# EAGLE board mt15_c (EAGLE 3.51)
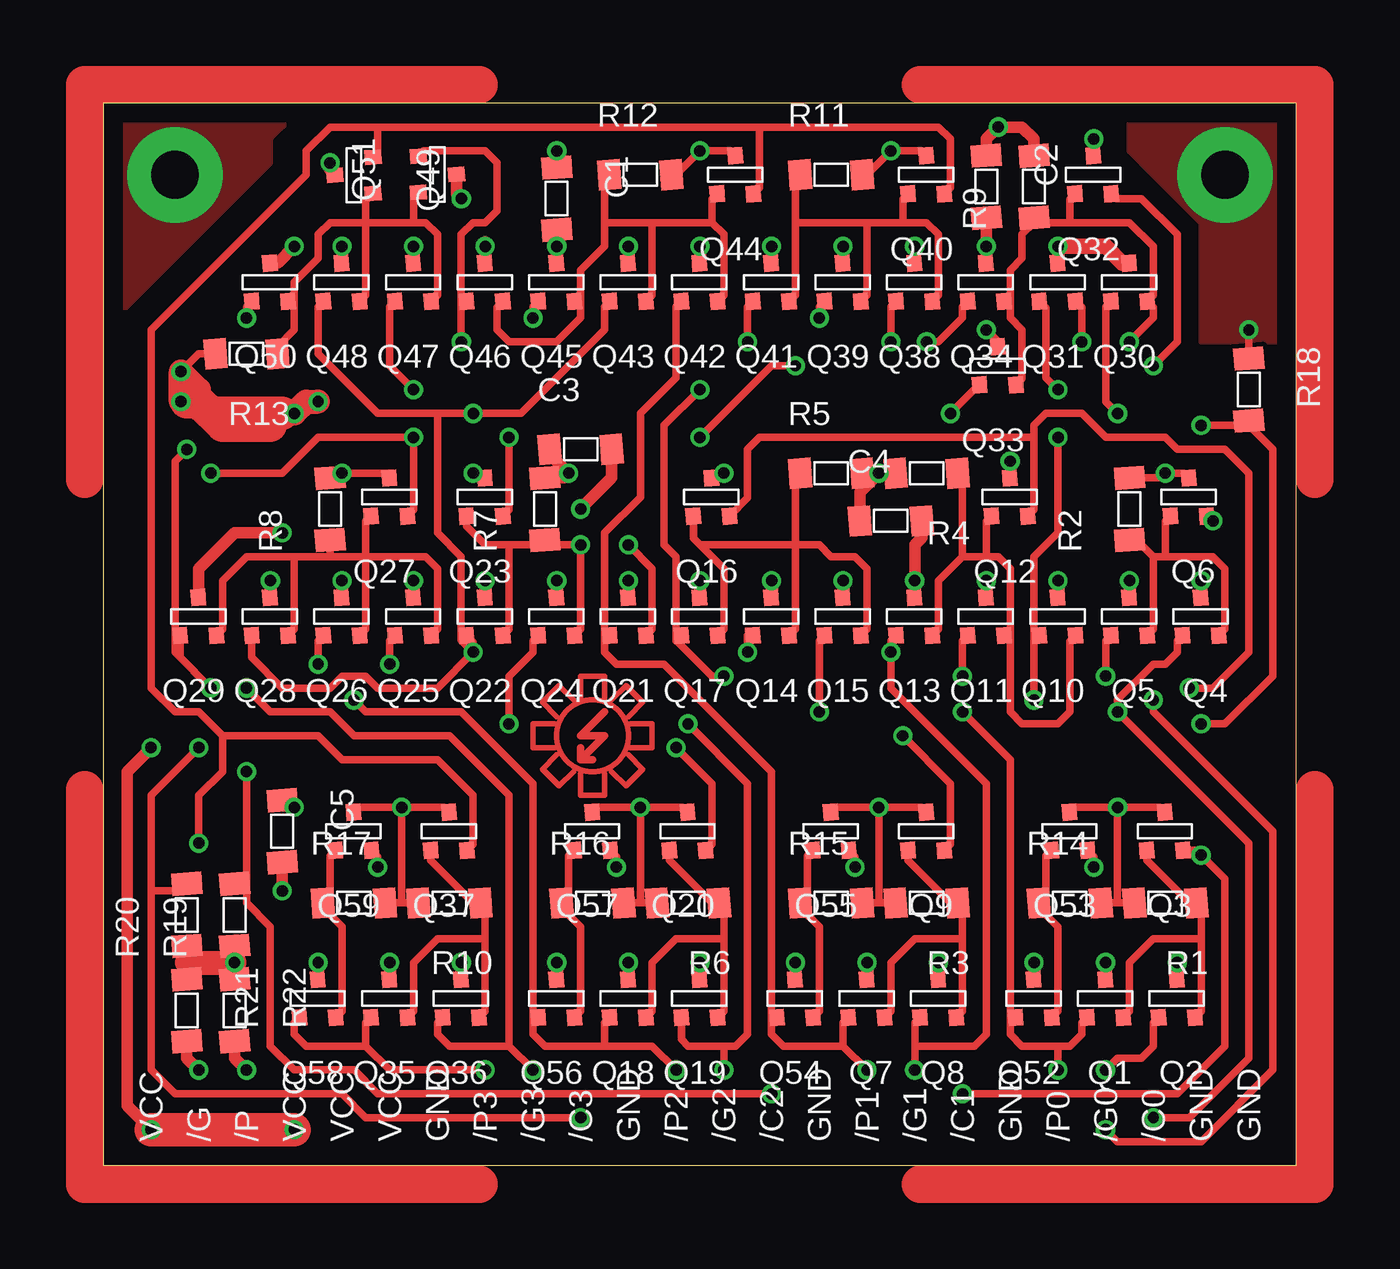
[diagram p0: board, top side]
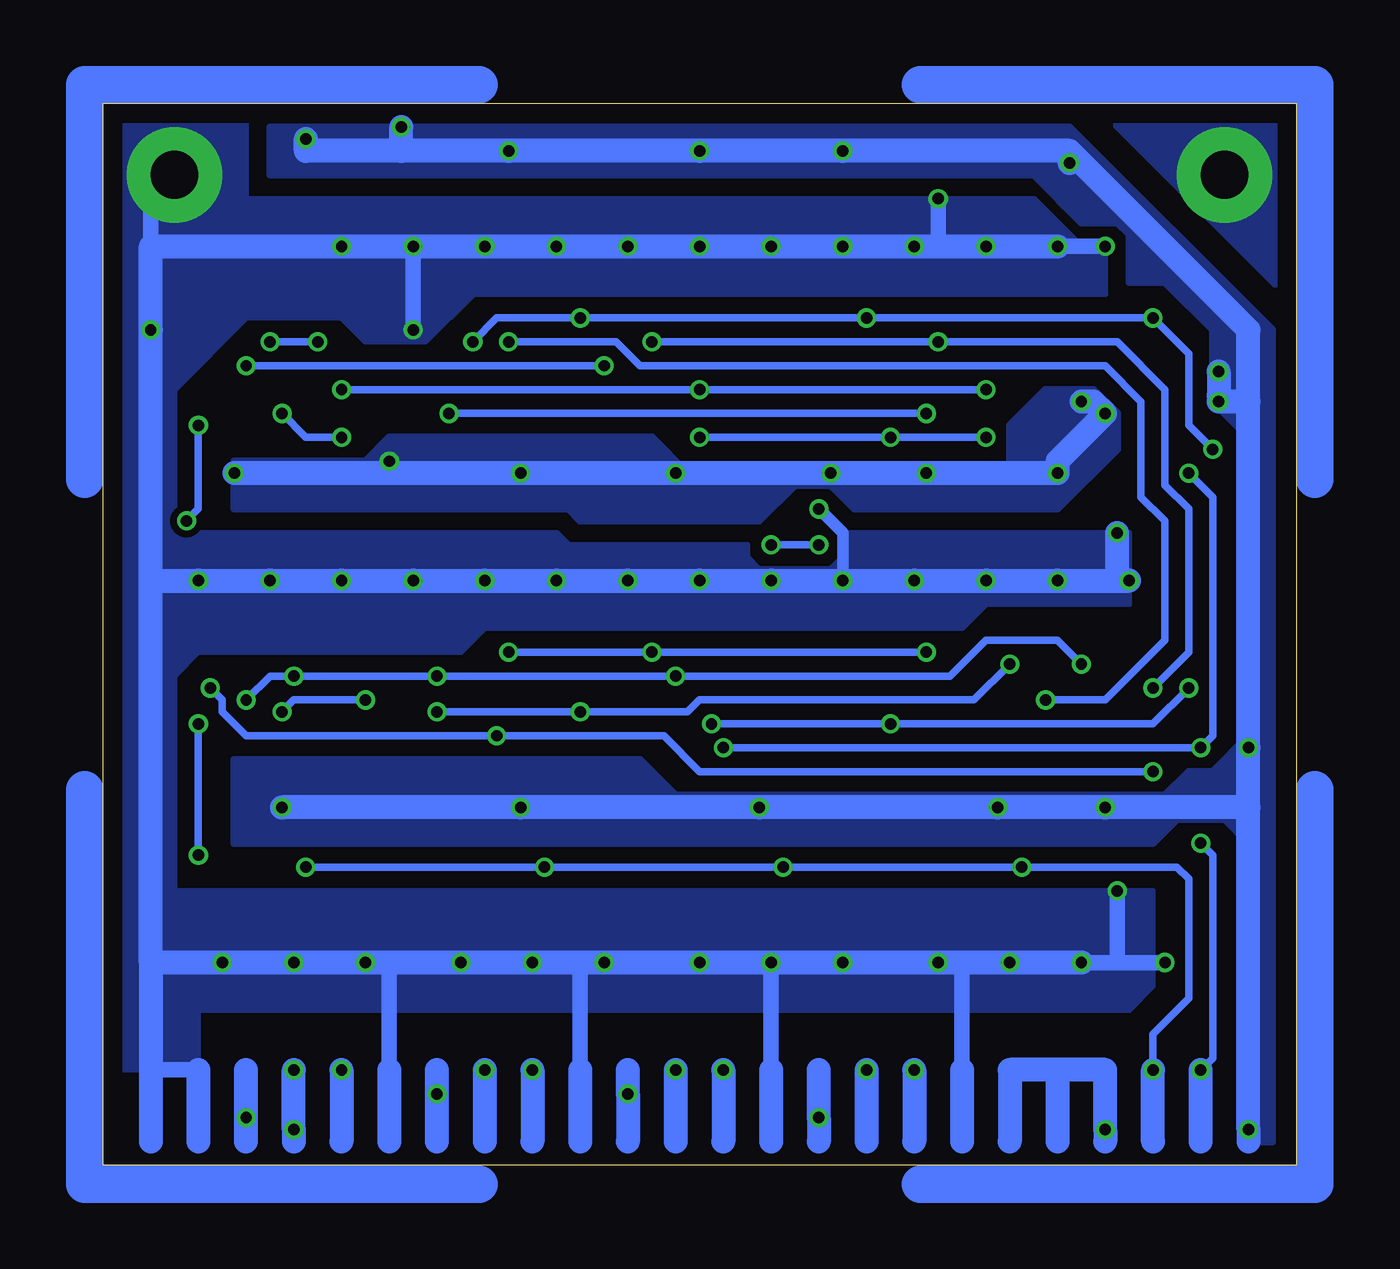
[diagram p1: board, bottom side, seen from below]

Size 63.48 x 56.5 mm. Coordinates in mm from the lower left corner, seen from the top.
Outline: 0,0 63.48,0 63.48,56.5 0,56.5 0,0
Copper layers used: Top, Bottom

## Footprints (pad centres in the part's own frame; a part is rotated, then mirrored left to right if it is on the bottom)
04 = smd 1.194 x 1.6 rotated 4.4:  1.651,0 | smd 1.194 x 1.6 rotated 4.3:  -1.651,0
T-23 = smd 0.787 x 0.889 rotated 4.4:  0.991,1.016 | smd 0.787 x 0.889 rotated 4.3:  -0.94,1.016 | smd 0.787 x 0.889 rotated 4.5:  0.025,-1.016

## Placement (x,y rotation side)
C1  100n  [04]  24.13,51.44 270 top
C2  100n  [04]  46.99,52.07 270 top
C3  100n  [04]  25.4,38.1 0 top
C4  100n  [04]  41.91,34.29 0 top
C5  100n  [04]  9.53,17.78 270 top
Q1  BC857  [T-23]  53.34,8.89 180 top
Q2  BC857  [T-23]  57.15,8.89 180 top
Q3  BC847  [T-23]  56.52,17.78 180 top
Q4  BC857  [T-23]  58.42,29.21 180 top
Q5  BC857  [T-23]  54.61,29.21 180 top
Q6  BC847  [T-23]  57.78,35.56 180 top
Q7  BC857  [T-23]  40.64,8.89 180 top
Q8  BC857  [T-23]  44.45,8.89 180 top
Q9  BC847  [T-23]  43.81,17.78 180 top
Q10  BC857  [T-23]  50.8,29.21 180 top
Q11  BC857  [T-23]  46.99,29.21 180 top
Q12  BC847  [T-23]  48.26,35.56 180 top
Q13  BC857  [T-23]  43.18,29.21 180 top
Q14  BC857  [T-23]  35.56,29.21 180 top
Q15  BC857  [T-23]  39.37,29.21 180 top
Q16  BC847  [T-23]  32.38,35.56 180 top
Q17  BC857  [T-23]  31.75,29.21 180 top
Q18  BC857  [T-23]  27.94,8.89 180 top
Q19  BC857  [T-23]  31.75,8.89 180 top
Q20  BC847  [T-23]  31.11,17.78 180 top
Q21  BC857  [T-23]  27.94,29.21 180 top
Q22  BC857  [T-23]  20.32,29.21 180 top
Q23  BC847  [T-23]  20.32,35.56 180 top
Q24  BC557  [T-23]  24.13,29.21 180 top
Q25  BC857  [T-23]  16.51,29.21 180 top
Q26  BC857  [T-23]  12.7,29.21 180 top
Q27  BC847  [T-23]  15.24,35.56 180 top
Q28  BC857  [T-23]  8.89,29.21 180 top
Q29  BC857  [T-23]  5.08,29.21 180 top
Q30  BC857  [T-23]  54.61,46.99 180 top
Q31  BC857  [T-23]  50.8,46.99 180 top
Q32  BC847  [T-23]  52.7,52.7 180 top
Q33  BC857  [T-23]  47.62,42.55 180 top
Q34  BC857  [T-23]  46.99,46.99 180 top
Q35  BC857  [T-23]  15.24,8.89 180 top
Q36  BC857  [T-23]  19.05,8.89 180 top
Q37  BC847  [T-23]  18.41,17.78 180 top
Q38  BC857  [T-23]  43.18,46.99 180 top
Q39  BC857  [T-23]  39.37,46.99 180 top
Q40  BC847  [T-23]  43.81,52.7 180 top
Q41  BC857  [T-23]  35.56,46.99 180 top
Q42  BC857  [T-23]  31.75,46.99 180 top
Q43  BC857  [T-23]  27.94,46.99 180 top
Q44  BC847  [T-23]  33.66,52.7 180 top
Q45  BC857  [T-23]  24.13,46.99 180 top
Q46  BC857  [T-23]  20.32,46.99 180 top
Q47  BC857  [T-23]  16.51,46.99 180 top
Q48  BC857  [T-23]  12.7,46.99 180 top
Q49  BC847  [T-23]  13.34,52.7 270 top
Q50  BC857  [T-23]  8.89,46.99 180 top
Q51  BC857  [T-23]  17.78,52.7 90 top
Q52  BC857  [T-23]  49.53,8.89 180 top
Q53  BC847  [T-23]  51.44,17.78 180 top
Q54  BC857  [T-23]  36.83,8.89 180 top
Q55  BC847  [T-23]  38.73,17.78 180 top
Q56  BC857  [T-23]  24.13,8.89 180 top
Q57  BC847  [T-23]  26.04,17.78 180 top
Q58  BC857  [T-23]  11.43,8.89 180 top
Q59  BC847  [T-23]  13.34,17.78 180 top
R1  390  [04]  56.52,13.97 180 top
R2  390  [04]  54.61,34.92 90 top
R3  390  [04]  43.81,13.97 180 top
R4  390  [04]  43.81,36.83 180 top
R5  390  [04]  38.73,36.83 0 top
R6  390  [04]  31.11,13.97 180 top
R7  390  [04]  23.5,34.92 90 top
R8  390  [04]  12.06,34.92 90 top
R9  390  [04]  49.53,52.07 90 top
R10  390  [04]  18.41,13.97 180 top
R11  390  [04]  38.73,52.7 0 top
R12  390  [04]  28.57,52.7 0 top
R13  390  [04]  7.62,43.18 180 top
R14  390  [04]  51.44,13.97 0 top
R15  390  [04]  38.73,13.97 0 top
R16  390  [04]  26.04,13.97 0 top
R17  390  [04]  13.34,13.97 0 top
R18  330  [04]  60.96,41.27 270 top
R19  330  [04]  6.99,13.34 90 top
R20  330  [04]  4.45,13.34 90 top
R21  330  [04]  4.45,8.26 270 top
R22  330  [04]  6.99,8.26 270 top
U$46  []  26.04,22.86 0 top

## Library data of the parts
C1-C4 Q1-Q59 R1-R22 = SMD
C5 = DISCRETE
U$46 = TAF

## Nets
!C0: Q4. Q10. Q30.
!C1: Q3. Q6. R18.
!C2: Q9. Q12. Q16. R19.
!C3: Q20. Q23. Q27. Q32. R20.
!G: Q37. Q40. Q44. Q49. R21.
!G0: Q2. Q5. Q11. Q17. Q26. Q31. Q47.
!G1: Q8. Q13. Q14. Q22. Q28. Q33. Q43. Q48.
!G2: Q19. Q24. Q29. Q34. Q39. Q45. Q50.
!G3: Q36. Q41. Q46. Q51.
!P: Q53. Q55. Q57. Q59. R22.
!P0: Q1. Q15. Q25. Q52.
!P1: Q7. Q21. Q42. Q54.
!P2: Q18. Q38. Q56.
!P3: Q35. Q58.
GND: C1. C2. C3. C4. C5. Q1. Q2. Q4. Q5. Q7. Q8. Q10. Q11. Q13. Q14. Q15. Q17. Q18. Q19. Q21. Q22. Q24. Q25. Q26. Q28. Q29. Q30. Q31. Q33. Q34. Q35. Q36. Q38. Q39. Q41. Q42. Q43. Q45. Q46. Q47. Q48. Q50. Q51. Q52. Q54. Q56. Q58. R18. R19. R20. R21. R22.
N$9: Q1. Q2. Q3. R1.
N$10: Q7. Q8. Q9. R3.
N$11: Q4. Q5. Q6. R2.
N$12: Q10. Q11. Q12. Q13. R4.
N$13: Q14. Q15. Q16. Q17. R5.
N$14: Q18. Q19. Q20. R6.
N$15: Q21. Q22. Q23. Q24. R7.
N$16: Q25. Q26. Q27. Q28. Q29. R8.
N$17: Q30. Q31. Q32. Q33. Q34. R9.
N$18: Q35. Q36. Q37. R10.
N$19: Q38. Q39. Q40. Q41. R11.
N$20: Q42. Q43. Q44. Q45. Q46. R12.
N$21: Q47. Q48. Q49. Q50. Q51. R13.
N$22: Q52. Q53. R14.
N$24: Q54. Q55. R15.
N$25: Q56. Q57. R16.
N$26: Q58. Q59. R17.
VCC: C1. C2. C3. C4. C5. Q3. Q6. Q9. Q12. Q16. Q20. Q23. Q27. Q32. Q37. Q40. Q44. Q49. Q53. Q55. Q57. Q59. R1. R2. R3. R4. R5. R6. R7. R8. R9. R10. R11. R12. R13. R14. R15. R16. R17.

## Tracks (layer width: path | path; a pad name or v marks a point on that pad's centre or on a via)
!C0  (via drill 0.61 pad 1.02)
  Top 0.406: v55.88,2.54 57.78,2.54 60.96,5.71 60.96,17.14 v53.98,24.13 53.98,24.77 55.88,26.67 56.52,26.67 57.15,27.3 57.15,27.91 57.43,28.19 | 49.81,28.19 49.53,27.91 49.53,27.3 | v49.53,24.77 49.53,27.3 | 49.53,27.3 49.53,32.38 50.8,33.66 v50.8,38.73 | 53.62,45.97 53.34,45.7 53.34,40.64 v53.98,40.01
  Bottom 0.406: v53.98,24.13 53.34,24.77 v49.53,24.77 | v53.98,40.01 52.7,38.73 v50.8,38.73
  Bottom 1.27: 55.88,1.27 v55.88,2.54 55.88,5.08
!C1  (via drill 0.61 pad 1.02)
  Top 0.406: v45.72,3.81 57.15,3.81 59.69,6.35 59.69,15.24 v58.42,16.51 58.17,16.76 57.45,16.76 | v58.42,23.5 59.69,23.5 62.23,26.04 62.23,38.1 60.96,39.37 | 60.96,39.37 v58.42,39.37 | 58.73,34.54 58.8,34.54 v59.05,34.29 | 60.96,39.37 60.96,39.62
  Bottom 0.406: v58.42,16.51 v58.42,23.5 | v59.05,34.29 58.42,34.92 v58.42,39.37
  Bottom 1.27: 45.72,1.27 v45.72,3.81 45.72,5.08
!C2  (via drill 0.61 pad 1.02)
  Top 0.406: v35.56,3.81 14.61,3.81 13.34,5.08 10.16,5.08 8.89,6.35 8.89,12.7 7.62,13.97 7.62,14.61 | 6.99,14.99 7.37,14.61 7.62,14.61 | 7.62,14.61 v7.62,20.95 | 44.76,16.76 45.09,17.09 45.09,20.32 v42.55,22.86 | v57.78,25.4 59.05,25.4 60.96,27.3 60.96,36.83 59.69,38.1 57.15,38.1 56.52,38.73 53.34,38.73 52.07,40.01 50.16,40.01 49.53,39.37 49.53,38.73 | 49.2,34.54 49.53,34.87 49.53,38.73 | 33.33,34.54 34.29,35.51 34.29,38.1 34.92,38.73 49.53,38.73
  Bottom 0.406: v7.62,20.95 31.75,20.95 33.66,22.86 v42.55,22.86 55.88,22.86 57.15,24.13 57.15,24.77 v57.78,25.4
  Bottom 1.27: 35.56,1.27 v35.56,3.81 35.56,5.08
!C3  (via drill 0.61 pad 1.02)
  Top 0.406: v25.4,2.54 13.97,2.54 12.7,3.81 3.81,3.81 2.54,5.08 2.54,14.61 | 2.54,14.61 2.54,19.68 v5.08,22.23 | 4.45,14.99 4.06,14.61 2.54,14.61 | 32.05,16.76 32.38,17.09 32.38,20.32 v30.48,22.23 | 16.18,34.54 16.51,34.87 v16.51,38.73 11.43,38.73 9.53,36.83 v5.71,36.83 | 21.26,34.54 21.59,34.87 v21.59,38.73 | v31.75,38.73 35.56,42.55 v36.83,42.55 | v55.88,42.55 57.15,43.81 57.15,49.53 55.24,51.44 53.9,51.44 53.65,51.69
  Bottom 0.406: v30.48,22.23 v5.08,22.23 4.45,22.86 4.45,35.56 v5.71,36.83 | v16.51,38.73 v21.59,38.73 v31.75,38.73 | v36.83,42.55 v55.88,42.55
  Bottom 1.27: 25.4,1.27 v25.4,2.54 25.4,5.08
!G  (via drill 0.61 pad 1.02)
  Top 0.406: 19.36,16.76 19.68,17.09 19.68,19.68 17.78,21.59 12.7,21.59 11.43,22.86 6.35,22.86 | 6.35,22.86 6.35,20.95 5.08,19.68 v5.08,17.14 | 6.35,22.86 5.08,24.13 3.81,24.13 2.54,25.4 2.54,44.45 10.79,52.7 10.79,53.98 12.06,55.24 14.61,55.24 | 14.61,55.24 34.92,55.24 | 34.59,51.69 34.92,52.02 34.92,55.24 | 44.76,51.69 45.09,52.02 45.09,54.61 44.45,55.24 34.92,55.24 | 14.35,53.65 14.61,53.9 14.61,55.24
  Top 0.61: v5.08,5.08 4.45,5.71 4.45,6.6
  Bottom 0.406: v5.08,5.08 4.45,5.71 4.45,16.51 v5.08,17.14
  Bottom 1.27: 5.08,1.27 v5.08,5.08
!G0  (via drill 0.61 pad 1.02)
  Top 0.406: v53.34,5.08 53.98,5.71 55.24,5.71 55.88,6.35 55.88,7.59 56.16,7.87 | v53.34,1.91 53.98,1.27 58.42,1.27 62.23,5.08 62.23,17.78 55.88,24.13 v55.88,24.77 | 53.62,28.19 53.34,27.91 v53.34,26.04 | 11.71,28.19 11.43,27.91 v11.43,26.67 | 30.76,28.19 30.48,27.91 30.48,27.94 | 46,28.19 45.72,27.91 v45.72,26.04 | v33.02,26.04 32.38,26.04 30.48,27.94 | 30.48,27.94 30.48,32.38 29.84,33.02 29.84,39.37 v31.75,41.27 | 15.52,45.97 15.24,45.7 15.24,42.55 v16.51,41.27 | 49.81,45.97 50.16,45.62 50.16,41.91 v50.8,41.27
  Bottom 0.406: v55.88,24.77 54.61,26.04 v53.34,26.04 v45.72,26.04 v33.02,26.04 18.41,26.04 16.51,27.94 12.7,27.94 v11.43,26.67 | v50.8,41.27 v31.75,41.27 v16.51,41.27
  Bottom 1.27: 53.34,1.27 v53.34,1.91 v53.34,5.08
!G1  (via drill 0.61 pad 1.02)
  Top 0.406: 43.46,7.87 43.18,7.59 43.18,6.35 | 43.18,6.35 v43.18,5.08 | 43.18,6.35 46.35,6.35 46.99,6.99 46.99,20.32 41.91,25.4 v41.91,27.3 41.91,27.91 42.19,28.19 | 7.9,28.19 7.9,27.03 9.53,25.4 12.06,25.4 12.7,26.04 13.97,26.04 14.61,25.4 17.78,25.4 v19.68,27.3 | 19.33,28.19 19.68,27.84 v19.68,27.3 | v19.68,27.3 19.05,27.94 19.05,32.38 17.78,33.66 17.78,40.01 | 11.71,45.97 11.43,45.7 11.43,43.18 14.61,40.01 17.78,40.01 | 17.78,40.01 v19.68,40.01 22.23,40.01 26.67,44.45 26.67,45.7 26.95,45.97 | 34.57,28.19 34.29,28.19 v34.29,27.3 | 46.63,41.53 46.61,41.53 v45.09,40.01
  Bottom 0.406: v19.68,27.3 v34.29,27.3 v41.91,27.3 | v19.68,40.01 v45.09,40.01
  Bottom 1.27: v43.18,5.08 43.18,1.27
!G2  (via drill 0.61 pad 1.02)
  Top 0.406: 30.76,7.87 30.76,6.71 31.11,6.35 33.02,6.35 | 33.02,6.35 33.66,6.35 34.29,6.99 34.29,20.32 v31.11,23.5 | 33.02,6.35 v33.02,5.08 | 23.14,28.19 22.86,27.91 22.86,27.3 21.59,26.04 v21.59,23.5 | 4.09,28.19 4.09,27.03 v5.71,25.4 3.81,27.3 3.81,37.47 v4.45,38.1 | 7.9,45.97 7.62,45.7 v7.62,45.09 | 23.14,45.97 22.86,45.7 v22.86,45.09 | 38.38,45.97 38.1,45.7 v38.1,45.09 | 46,45.97 45.72,45.7 45.72,45.09 44.45,43.81 v43.81,43.81
  Bottom 0.406: v31.11,23.5 v21.59,23.5 7.62,23.5 v5.71,25.4 | v43.81,43.81 42.55,45.09 v38.1,45.09 v22.86,45.09 v7.62,45.09 5.71,43.18 5.71,39.37 v4.45,38.1
  Bottom 1.27: v33.02,5.08 33.02,1.27
!G3  (via drill 0.61 pad 1.02)
  Top 0.406: 18.06,7.87 17.78,7.59 17.78,6.99 18.41,6.35 21.59,6.35 | 21.59,6.35 v22.86,5.08 | 21.59,6.35 21.59,19.68 18.41,22.86 13.34,22.86 12.06,24.13 8.89,24.13 v7.62,25.4 | 34.57,45.97 34.29,45.7 v34.29,43.81 | 19.33,45.97 19.05,45.7 19.05,45.09 | v19.05,43.81 19.05,45.09 | 19.05,45.09 19.05,49.53 19.68,50.16 20.32,50.16 20.95,50.8 20.95,53.34 20.32,53.98 17.04,53.98 16.76,53.7
  Bottom 0.406: v7.62,25.4 5.71,27.3 5.71,34.92 6.99,36.2 6.99,41.27 9.53,43.81 v19.05,43.81 v34.29,43.81
  Bottom 1.27: v22.86,5.08 22.86,1.27
!P  (via drill 0.61 pad 1.02)
  Top 0.406: 14.28,16.76 14.61,16.43 v14.61,15.88 | 26.98,16.76 27.3,16.43 v27.3,15.88 | 39.67,16.76 40.01,16.43 v40.01,15.88 | 52.38,16.76 52.7,16.43 v52.7,15.88
  Top 0.61: v7.62,5.08 6.99,5.71 6.99,6.6
  Bottom 0.406: v7.62,5.08 7.62,6.99 5.71,8.89 5.71,15.24 6.35,15.88 v14.61,15.88 v27.3,15.88 v40.01,15.88 v52.7,15.88
  Bottom 1.27: 7.62,1.27 v7.62,5.08
!P0  (via drill 0.61 pad 1.02)
  Top 0.406: 48.54,7.87 48.26,7.59 48.26,6.99 | 48.26,6.99 48.9,6.35 50.8,6.35 | 50.8,6.35 51.44,6.35 52.07,6.99 52.07,7.59 52.35,7.87 | 50.8,6.35 v50.8,5.08 | v45.72,24.13 48.26,21.59 48.26,6.99 | 38.38,28.19 38.1,27.91 v38.1,24.13 | 15.52,28.19 15.24,27.91 v15.24,26.67
  Bottom 0.406: v45.72,24.13 v38.1,24.13 32.38,24.13 31.75,24.77 17.14,24.77 v15.24,26.67
  Bottom 1.27: v50.8,5.08 50.8,1.27
!P1  (via drill 0.61 pad 1.02)
  Top 0.406: 35.84,7.87 35.56,7.59 35.56,6.99 | 35.56,6.99 36.2,6.35 39.37,6.35 | 39.65,7.87 39.37,7.59 39.37,6.35 | 39.37,6.35 v40.64,5.08 | 26.95,28.19 26.67,27.91 26.67,27.3 | 26.67,27.3 27.3,26.67 29.84,26.67 35.56,20.95 35.56,6.99 | 30.76,45.97 30.48,45.7 30.48,41.91 28.57,40.01 28.57,35.56 26.67,33.66 26.67,27.3
  Bottom 1.27: v40.64,5.08 40.64,1.27
!P2  (via drill 0.61 pad 1.02)
  Top 0.406: 23.14,7.87 22.86,7.59 22.86,6.99 | 22.86,6.99 23.5,6.35 26.67,6.35 | 26.95,7.87 26.67,7.59 26.67,6.35 | v30.48,5.08 29.21,6.35 26.67,6.35 | 22.86,6.99 22.86,20.32 19.05,24.13 13.97,24.13 v13.34,24.77 | 42.19,45.97 41.91,45.7 v41.91,43.81
  Bottom 0.406: v13.34,24.77 10.16,24.77 6.99,27.94 6.99,34.29 8.26,35.56 8.26,40.64 10.16,42.55 34.92,42.55 36.2,43.81 v41.91,43.81
  Bottom 1.27: v30.48,5.08 30.48,1.27
!P3  (via drill 0.61 pad 1.02)
  Top 0.406: 10.44,7.87 10.16,7.59 10.16,6.99 10.79,6.35 13.97,6.35 | 14.25,7.87 13.97,7.59 13.97,6.35 | v20.32,5.08 15.24,5.08 13.97,6.35
  Bottom 1.27: v20.32,5.08 20.32,1.27
GND  (via drill 0.61 pad 1.02, 2.54 pad 5.08)
  Top 0.406: v60.96,44.45 R18. | Q33. 47.6,43.84 v46.99,44.45
  Top 0.61: Q58. 11.43,9.91 v11.43,10.79 | Q35. 15.24,9.91 v15.24,10.79 | Q36. 19.05,9.91 v19.05,10.79 | Q56. 24.13,9.91 v24.13,10.79 | Q18. 27.94,9.91 v27.94,10.79 | Q19. 31.75,9.91 v31.75,10.79 | Q54. 36.83,9.91 v36.83,10.79 | Q7. 40.64,9.91 v40.64,10.79 | Q8. 44.45,9.91 v44.45,10.79 | Q52. 49.53,9.91 v49.53,10.79 | Q2. 57.15,9.91 v57.15,10.79 | Q1. 53.34,9.91 v53.34,10.79 | R21. 4.45,10.79 R20. | R22. v6.99,10.79 R19. | Q29. 5.08,30.25 5.08,31.75 6.99,33.66 v9.53,33.66 | Q28. 8.89,30.25 v8.89,31.11 | Q26. 12.7,30.25 v12.7,31.11 | Q25. 16.51,30.25 v16.51,31.11 | Q22. 20.32,30.25 v20.32,31.11 | Q24. 24.13,30.25 v24.13,31.11 | Q21. 27.94,30.25 v27.94,31.11 | Q17. 31.75,30.25 v31.75,31.11 | Q14. 35.56,30.25 v35.56,31.11 | Q15. 39.37,30.25 v39.37,31.11 | Q13. 43.18,30.25 v43.18,31.11 43.18,33.02 43.56,33.4 43.56,34.29 | Q11. 46.99,30.25 v46.99,31.11 | Q10. 50.8,30.25 v50.8,31.11 | Q5. 54.61,30.25 v54.61,31.11 | Q4. 58.42,30.25 v58.42,31.11 | Q31. 50.8,48.03 v50.8,48.9 | Q34. 46.99,48.03 v46.99,48.9 46.99,50.42 | Q38. 43.18,48.03 v43.18,48.9 | Q39. 39.37,48.03 v39.37,48.9 | Q41. 35.56,48.03 v35.56,48.9 | Q42. 31.75,48.03 v31.75,48.9 | Q50. 8.89,48.03 9.3,48.03 v10.16,48.9 | Q48. 12.7,48.03 v12.7,48.9 | Q47. 16.51,48.03 v16.51,48.9 | Q46. 20.32,48.03 v20.32,48.9 20.32,49.15 | Q45. 24.13,48.03 v24.13,48.9 24.13,49.78 | Q43. 27.94,48.03 v27.94,48.9 | 27.05,38.1 27.05,36.58 v25.4,34.92 | v9.53,14.61 9.53,16.13 | Q51. 18.8,51.69 v19.05,51.44
  Top 0.813: Q30. 54.23,48.01 53.34,48.9 v50.8,48.9
  Top 1.27: 4.45,10.79 v6.99,10.79
  Bottom 0.61: v25.4,34.92 24.13,33.66 v24.13,31.11
  Bottom 0.813: v6.99,10.79 9.53,10.79 | 9.53,10.79 v9.53,14.61 | 9.53,10.79 v11.43,10.79 | v12.7,48.9 v10.16,48.9 | 60.96,5.08 58.42,5.08 | 38.1,10.79 38.1,5.08 | 48.26,10.79 48.26,5.08 | v27.94,10.79 27.94,5.08 | 17.78,10.79 17.78,5.08 | v46.99,48.9 v46.99,44.45 | 60.96,48.9 60.96,51.44 v59.69,52.7 | 19.05,48.9 v19.05,51.44
  Bottom 1.27: v11.43,10.79 v15.24,10.79 17.78,10.79 v19.05,10.79 v24.13,10.79 v27.94,10.79 v31.75,10.79 v36.83,10.79 38.1,10.79 v40.64,10.79 v44.45,10.79 48.26,10.79 v49.53,10.79 v53.34,10.79 v57.15,10.79 60.96,10.79 | 60.96,10.79 60.96,31.11 | 60.96,31.11 v60.96,44.45 60.96,48.9 v50.8,48.9 v46.99,48.9 v43.18,48.9 v39.37,48.9 v35.56,48.9 v31.75,48.9 v27.94,48.9 v24.13,48.9 v20.32,48.9 19.05,48.9 v16.51,48.9 v12.7,48.9 | 9.53,31.11 v9.53,33.66 | 9.53,31.11 v12.7,31.11 v16.51,31.11 v20.32,31.11 v24.13,31.11 v27.94,31.11 v31.75,31.11 v35.56,31.11 v39.37,31.11 v43.18,31.11 v46.99,31.11 v50.8,31.11 v54.61,31.11 v58.42,31.11 60.96,31.11 | 9.53,31.11 v8.89,31.11 | 60.96,10.79 60.96,5.08 60.96,1.27 | 58.42,5.08 58.42,1.27 | 38.1,5.08 38.1,1.27 | 48.26,5.08 48.26,1.27 | 27.94,5.08 27.94,1.27 | 17.78,5.08 17.78,1.27
  pour Bottom (isolate 0.356): 62.87,5.08 58.42,5.08 58.42,8.26 8.89,8.26 7.62,9.53 7.62,14.61 59.69,14.61 59.69,26.04 58.42,27.3 44.45,27.3 43.18,28.57 17.78,28.57 16.51,29.84 8.89,29.84 8.89,33.66 24.13,33.66 24.13,32.38 24.77,31.75 28.57,31.75 29.21,32.38 29.21,33.02 38.73,33.02 39.37,33.66 59.69,33.66 59.69,41.27 55.88,45.09 50.8,45.09 49.53,43.81 46.35,43.81 43.81,46.35 10.16,46.35 10.16,48.9 11.43,48.9 13.97,51.44 55.88,51.44 55.88,55.88 62.87,55.88
  pour Top (isolate 0.356): 54.61,55.88 62.87,55.88 62.87,43.81 58.42,43.81 58.42,50.16 54.61,53.98
GND1  (via drill 2.54 pad 5.08)
  other vias: 3.81,52.7
  pour Top (isolate 0.356): 0.64,55.88 0.64,45.09 8.89,53.34 8.89,54.61 10.16,55.88
  pour Bottom (isolate 0.356): 0.64,55.88 0.64,45.72 0.64,46.35 10.16,55.88
N$1
  Top 2: 20,-1 -1,-1 -1,20
N$2
  Top 2: 43.48,-1 64.48,-1 64.48,20
N$3
  Top 2: 20,57.5 -1,57.5 -1,36.5
N$4
  Top 2: 64.48,36.5 64.48,57.5 43.48,57.5
N$5
  Bottom 2: 20,-1 -1,-1 -1,20
N$6
  Bottom 2: 43.48,-1 64.48,-1 64.48,20
N$7
  Bottom 2: 20,57.5 -1,57.5 -1,36.5
N$8
  Bottom 2: 64.48,36.5 64.48,57.5 43.48,57.5
N$9
  Top 0.406: 58.09,7.87 58.42,8.2 58.42,12.06 | 54.28,7.87 54.61,8.2 54.61,10.79 55.88,12.06 58.42,12.06 | 58.42,12.06 58.42,13.72 R1. 57.78,13.97 55.52,16.23 55.52,16.76
N$10
  Top 0.406: 41.58,7.87 41.91,8.2 41.91,10.79 43.18,12.06 45.72,12.06 | 45.39,7.87 45.72,8.2 45.72,12.06 | 45.72,12.06 45.72,13.72 R3. 45.09,13.97 42.82,16.23 42.82,16.76
N$11
  Top 0.406: 55.55,28.19 55.88,28.52 55.88,32.38 | 55.88,32.38 56.52,32.38 | 56.52,32.38 59.05,32.38 59.69,31.75 59.69,28.52 59.36,28.19 | 56.79,34.54 56.52,34.27 56.52,32.38 | R2. 54.99,33.27 55.88,32.38
N$12
  Top 0.406: 44.12,28.19 44.45,28.52 44.45,31.11 45.72,32.38 | 45.72,32.38 46.99,32.38 | 46.99,32.38 47.62,32.38 48.26,31.75 48.26,29.21 | 47.93,28.19 48.26,28.52 48.26,29.21 | 47.27,34.54 46.99,34.27 46.99,32.38 | R4. 45.72,36.58 45.72,32.38 | 51.74,28.19 51.44,27.89 51.44,24.13 50.8,23.5 48.9,23.5 48.26,24.13 48.26,29.21
N$13
  Top 0.406: 32.69,28.19 33.02,28.52 33.02,31.75 31.75,33.02 | 31.75,33.02 36.83,33.02 | 36.83,33.02 38.1,33.02 38.73,32.38 40.01,32.38 40.64,31.75 40.64,28.52 40.31,28.19 | 36.5,28.19 36.83,28.52 36.83,33.02 | R5. 36.83,36.58 36.83,33.02 | 31.39,34.54 31.39,33.38 31.75,33.02
N$14
  Top 0.406: 28.88,7.87 29.21,8.2 29.21,10.79 30.48,12.06 33.02,12.06 | 32.69,7.87 33.02,8.2 33.02,12.06 | 33.02,12.06 33.02,13.72 R6. 32.38,13.97 30.12,16.23 30.12,16.76
N$15  (via drill 0.61 pad 1.02)
  Top 0.406: 21.26,28.19 21.59,28.52 21.59,33.02 | 21.59,33.02 23.5,33.02 | 23.5,33.02 v25.4,33.02 25.4,28.52 25.07,28.19 | 28.88,28.19 29.21,28.52 29.21,31.75 v27.94,33.02 | 23.5,33.02 R7. | 21.59,33.02 20.32,33.02 19.33,34.01 19.33,34.54
  Bottom 0.406: v25.4,33.02 v27.94,33.02
N$16
  Top 0.406: 6.02,28.19 6.35,28.52 6.35,31.11 7.62,32.38 10.16,32.38 | 10.16,32.38 12.06,32.38 | 12.06,32.38 13.97,32.38 | 13.97,32.38 17.14,32.38 17.78,31.75 17.78,28.52 17.45,28.19 | 13.64,28.19 13.97,28.52 13.97,32.38 | 9.83,28.19 10.16,28.52 10.16,32.38 | 12.06,32.38 R8. | 14.25,34.54 13.97,34.27 13.97,32.38
N$17  (via drill 0.61 pad 1.02)
  Top 0.406: 48.26,46.3 47.93,45.97 | 48.26,46.3 48.26,47.62 48.9,48.26 48.9,49.53 49.53,50.16 | 49.53,50.16 51.44,50.16 | 51.44,50.16 54.61,50.16 55.88,48.9 55.88,46.3 55.55,45.97 55.88,45.64 55.88,45.09 v54.61,43.81 | 51.71,51.69 51.44,51.41 51.44,50.16 | 48.56,41.53 48.9,41.86 48.9,44.45 48.26,45.09 48.26,46.3 | 51.74,45.97 52.07,45.64 v52.07,43.81 | 49.53,50.16 R9.
  Bottom 0.406: v54.61,43.81 v52.07,43.81
N$18
  Top 0.406: 16.18,7.87 16.51,8.2 16.51,10.79 17.78,12.06 20.32,12.06 | 19.99,7.87 20.32,8.2 20.32,12.06 | 20.32,12.06 20.32,13.72 R10. 19.68,13.97 17.42,16.23 17.42,16.76
N$19
  Top 0.406: 36.5,45.97 36.83,46.3 36.83,50.16 | 36.83,50.16 40.64,50.16 | 40.31,45.97 40.64,46.3 40.64,50.16 | 40.64,50.16 42.55,50.16 | 44.12,45.97 44.45,46.3 44.45,49.53 43.81,50.16 42.55,50.16 | 42.82,51.69 42.55,51.41 42.55,50.16 | R11. 36.83,52.45 36.83,50.16
N$20
  Top 0.406: 26.67,50.16 29.21,50.16 | 32.69,45.97 33.02,46.3 33.02,49.53 32.38,50.16 | 28.88,45.97 29.21,46.3 29.21,50.16 | 29.21,50.16 32.38,50.16 | 25.07,45.97 25.4,46.3 25.4,46.35 | 25.4,46.35 25.4,47.62 26.67,48.9 26.67,50.16 | 32.66,51.69 32.38,51.41 32.38,50.16 | R12. 26.67,52.45 26.67,50.16 | 21.26,45.97 20.95,45.67 20.95,44.45 21.59,43.81 24.13,43.81 25.4,45.09 25.4,46.35
N$21
  Top 0.406: 13.97,50.16 12.06,50.16 11.43,49.53 11.43,48.26 10.16,46.99 | 17.45,45.97 17.78,46.3 17.78,49.53 17.14,50.16 16.51,50.16 | 13.64,45.97 13.97,46.3 13.97,50.16 | 9.83,45.97 10.16,46.3 10.16,46.99 | 13.97,50.16 16.51,50.16 | 16.76,51.77 16.51,51.51 16.51,50.16 | 14.35,51.71 13.97,51.33 13.97,50.16 | 10.16,46.99 10.16,44.45 9.27,43.56 R13.
N$22
  Top 0.406: 50.47,7.87 50.8,8.2 50.8,12.7 49.78,13.72 R14. 50.16,14.35 50.16,16.48 50.44,16.76
N$24
  Top 0.406: 37.77,7.87 38.1,8.2 38.1,12.7 37.08,13.72 R15. 37.47,14.35 37.47,16.48 37.74,16.76
N$25
  Top 0.406: 25.07,7.87 25.4,8.2 25.4,12.7 24.38,13.72 R16. 24.77,14.35 24.77,16.48 25.04,16.76
N$26
  Top 0.406: 12.37,7.87 12.7,8.2 12.7,12.7 11.68,13.72 R17. 12.06,14.35 12.06,16.48 12.34,16.76
VCC  (via drill 0.61 pad 1.02)
  Top 0.406: 15.88,13.97 14.99,13.97 | 15.88,13.97 16.76,13.97 | 28.57,13.97 27.69,13.97 | 28.57,13.97 29.46,13.97 | 41.27,13.97 40.39,13.97 | 41.27,13.97 42.16,13.97 | 53.98,13.97 53.09,13.97 | 53.98,13.97 54.86,13.97 | Q59. 13.56,19.05 v15.88,19.05 | Q37. 18.14,19.05 v15.88,19.05 | Q57. 26.26,19.05 v28.57,19.05 | Q20. 30.84,19.05 v28.57,19.05 | Q55. 38.96,19.05 v41.27,19.05 | Q9. 43.54,19.05 v41.27,19.05 | Q53. 51.66,19.05 v53.98,19.05 | Q3. 56.24,19.05 v53.98,19.05 | v53.98,19.05 53.98,13.97 | v41.27,19.05 41.27,13.97 | v28.57,19.05 28.57,13.97 | v15.88,19.05 15.88,13.97 | 42.55,36.83 42.16,36.83 v41.27,36.83 40.39,36.83 | Q6. 57.51,36.83 v56.52,36.83 56.26,36.58 54.61,36.58 | Q16. 32.77,36.58 v33.02,36.83 | Q27. 15.21,36.83 v12.7,36.83 12.06,36.83 12.06,36.58 | Q12. 48.26,36.6 v48.26,37.47 | Q40. 43.54,53.98 v41.91,53.98 40.64,52.7 40.39,52.7 | 30.23,52.7 30.48,52.7 v31.75,53.98 33.38,53.98 Q44. | Q32. 52.7,53.75 v52.7,54.61 | Q23. 20.04,36.83 v19.68,36.83 | 5.97,43.18 5.08,43.18 v4.13,42.23
  Top 0.61: C2. 46.99,54.61 v47.62,55.24 48.9,55.24 49.53,54.61 49.53,53.72 | C3. 23.75,37.85 v24.77,36.83 24.51,36.58 23.5,36.58 | C4. 40.26,35.81 v41.27,36.83 | C5. 9.53,19.68 v10.16,19.05 | v2.54,1.91 1.27,3.17 1.27,20.95 v2.54,22.23 | v24.13,53.98 C1. | Q49. 12.06,52.93 v12.06,53.34
  Top 1.27: 8.89,39.37 9.53,40.01 v10.16,40.01 10.79,40.64 v11.43,40.64 | 4.45,40.64 v4.13,40.64 v4.13,42.23 5.08,41.27
  Top 1.778: v2.54,1.91 v10.16,1.91 | 4.45,40.64 5.08,40.64 5.71,40.01 | 5.71,40.01 6.35,39.37 8.89,39.37 | 5.71,40.01 9.53,40.01
  Bottom 0.406: 48.26,36.83 v48.26,37.47
  Bottom 1.27: v53.98,19.05 v41.27,19.05 v28.57,19.05 v15.88,19.05 v10.16,19.05 2.54,19.05 | 2.54,1.27 v2.54,1.91 2.54,19.05 | 2.54,19.05 v2.54,22.23 2.54,40.64 | v56.52,36.83 48.26,36.83 v41.27,36.83 v33.02,36.83 v24.77,36.83 v19.68,36.83 v12.7,36.83 12.7,37.47 v10.16,40.01 10.79,40.64 v11.43,40.64 | 2.54,40.64 v4.13,40.64 | 47.62,53.98 v47.62,55.24 | 47.62,53.98 v41.91,53.98 v31.75,53.98 v24.13,53.98 12.06,53.98 | v52.7,54.61 52.7,53.98 47.62,53.98 | 12.06,53.98 v12.06,53.34 | 2.54,40.64 2.54,44.45 12.06,53.98 | 10.16,1.27 v10.16,1.91 10.16,5.08 12.7,5.08 | 15.24,1.27 15.24,5.08 12.7,5.08 | 12.7,5.08 12.7,1.27 | v4.13,42.23 4.13,40.96
  pour Bottom (isolate 0.356): 2.54,1.27 1.27,1.27 1.27,44.45 12.06,55.24 54.61,55.24 54.61,52.7 13.97,52.7 11.43,50.16 9.53,50.16 8.89,49.53 8.89,46.99 6.99,46.99 4.45,44.45 4.45,40.64 2.54,38.73 2.54,22.86 4.45,20.95 5.71,20.95 6.99,19.68 33.02,19.68 34.92,21.59 56.52,21.59 56.52,17.14 7.62,17.14 6.35,18.41 3.81,18.41 2.54,17.14
  pour Bottom (isolate 0.356): 9.53,38.1 9.53,40.01 10.79,41.27 13.34,41.27 15.24,39.37 15.24,36.83 32.38,36.83 34.29,38.73 48.26,38.73 49.53,37.47 56.52,37.47 56.52,34.92 38.73,34.92 38.1,34.29 28.57,34.29 26.67,36.2 24.77,36.2 23.5,34.92 12.7,34.92

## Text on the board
tNames: VCC | /G | /P | VCC | VCC | VCC | GND | /P3 | /G3 | /C3 | GND | /P2 | /G2 | /C2 | GND | /P1 | /G1 | /C1 | GND | /P0 | /G0 | /C0 | GND | GND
